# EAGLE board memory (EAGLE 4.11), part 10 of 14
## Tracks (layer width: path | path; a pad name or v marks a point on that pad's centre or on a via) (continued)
N$73  (via drill 0.61) (continued)
  Route2 0.254: v290.19,44.45 288.29,46.36 281.31,46.36 281.31,50.16 F18.F2 | v359.41,6.98 362.58,10.16 387.35,10.16 388.62,8.89 388.62,8.25 v387.99,7.62
  Route3 0.254: v324.49,4.44 328.3,4.44 330.83,1.9 359.41,1.9 v359.41,6.98
  Bottom 0.254: v392.43,12.06 393.06,11.43 398.14,11.43 404.5,17.78 410.85,17.78 417.83,24.77 420.37,24.77 F07.R2
N$74  (via drill 0.61)
  Top 0.254: C07.N2 420.37,237.49 420.37,232.41 C07.R2 | v404.5,77.47 406.4,75.56 406.4,52.7 v403.23,49.53
  Route2 0.254: v347.98,56.52 348.62,55.88 349.88,55.88 350.52,55.25 353.06,55.25 353.69,55.88 354.96,55.88 360.05,50.8 360.05,48.9 358.77,48.9 v357.5,47.62 | v373.38,38.73 381,46.36 381,48.9 v388.62,48.9 | v433.07,103.5 407.04,77.47 v404.5,77.47
  Route3 0.254: v357.5,47.62 359.41,45.72 361.95,45.72 361.95,40.01 360.68,38.73 366.39,33.02 367.67,33.02 v373.38,38.73 | F08.U2 410.85,16.51 409.57,17.78 409.57,34.29 398.78,45.09 398.78,46.99 F09.H2 | v426.72,212.72 426.72,217.17 425.45,218.44 425.45,229.23 424.18,230.5 424.18,234.31 C07.P2 | v430.53,212.72 430.53,208.28 434.98,203.84 434.98,173.99 433.7,172.72 433.7,170.18 434.98,168.91 434.98,145.41 438.15,142.24 438.15,108.58 v433.07,103.5
  Bottom 0.254: C07.R2 421,232.41 422.91,234.31 423.55,234.31 C07.P2 | v347.98,56.52 347.35,55.88 343.54,55.88 342.9,56.52 339.73,56.52 338.45,55.25 334.01,55.25 330.83,52.07 328.3,52.07 327.66,52.7 325.12,52.7 324.49,52.07 315.6,52.07 314.96,52.7 306.07,52.7 304.8,51.44 303.53,51.44 300.99,48.9 299.72,48.9 299.08,49.53 290.19,49.53 288.93,48.26 284.48,48.26 F18.H2 | v388.62,48.9 391.16,48.9 391.8,49.53 396.88,49.53 398.14,48.26 F09.H2 398.78,48.26 401.95,48.26 v403.23,49.53 | v430.53,212.72 v426.72,212.72
N$75  (via drill 0.61)
  Top 0.254: v243.21,344.17 243.21,354.97 A21.V2
  Route3 0.254: v133.35,345.44 133.35,343.54 130.18,340.36 130.18,313.06 128.91,311.79 B30.L2
  Bottom 0.254: v133.35,345.44 168.28,345.44 169.54,344.17 217.17,344.17 218.44,345.44 221.62,345.44 222.88,344.17 v243.21,344.17 | A21.U2 245.75,358.14 243.84,356.24 243.21,356.24 A21.V2
N$76  (via drill 0.61)
  Route3 0.254: v231.78,365.12 231.78,369.57 233.04,370.84 A22.P2
  Bottom 0.254: v231.78,365.12 231.78,363.86 238.76,363.86 240.03,362.59 242.57,362.59 A21.T2
N$77  (via drill 0.61)
  Top 0.254: v167.64,389.89 167.64,392.43 167,393.06 A27.F2
  Bottom 0.254: v167.64,389.89 168.28,389.25 173.35,389.25 175.9,386.72 177.8,386.72 179.07,385.45 187.96,385.45 188.59,386.08 197.49,386.08 198.12,385.45 200.66,385.45 201.29,386.08 206.38,386.08 207.65,384.81 A24.K2
N$78  (via drill 0.61)
  Top 0.254: v400.05,215.26 400.05,229.87 398.78,231.14 398.78,234.31 C09.P2
  Bottom 0.254: v400.05,215.26 379.1,215.26 378.46,214.63 350.52,214.63 349.25,215.9 332.74,215.9 332.11,216.53 332.11,218.44 C14.V2
N$79  (via drill 0.61)
  Top 0.254: v238.76,374.02 234.95,370.21 234.95,360.68 233.68,359.41 A22.U2
  Bottom 0.254: v238.76,374.02 241.94,377.19 245.75,377.19 A21.M2
N$80  (via drill 0.61)
  Top 0.254: D30.D2 128.91,194.31 130.18,195.58 130.18,219.71 131.44,220.98 131.44,221.61 C30.U2 | C32.D2 103.5,262.89 104.78,261.62 104.78,250.19 106.05,248.92 106.05,248.28 C32.K2 | C29.D2 141.6,262.89 142.88,261.62 142.88,249.56 144.15,248.28 C29.K2 | C30.N2 128.27,238.76 128.27,242.57 127,243.84 127,251.46 127.64,252.09 131.44,252.09 131.44,248.28 C30.K2 | v120.65,238.76 120.65,224.16 119.38,222.88 C31.U2
  Bottom 0.254: C32.U2 106.68,221.61 107.31,220.98 111.76,220.98 112.39,220.34 117.47,220.34 118.75,221.61 C31.U2 119.38,221.61 120.02,220.98 124.46,220.98 125.09,220.34 130.18,220.34 131.44,221.61 C30.U2 132.08,222.88 134.62,222.88 135.89,224.16 142.88,224.16 144.15,222.88 C29.U2 | C32.N2 103.5,238.76 104.78,240.03 109.86,240.03 111.12,238.76 115.57,238.76 C31.N2 116.2,238.76 116.84,239.39 120.65,239.39 | C29.N2 140.97,238.76 137.16,238.76 135.89,240.03 134.62,240.03 133.35,238.76 128.91,238.76 C30.N2 128.27,238.76 124.46,238.76 123.19,240.03 121.92,240.03 121.28,239.39 120.65,239.39 | C30.D2 128.91,264.16 130.18,265.43 135.89,265.43 137.79,263.53 140.97,263.53 C29.D2 | C32.D2 103.5,264.16 104.78,265.43 110.49,265.43 112.39,263.53 115.57,263.53 C31.D2 | C32.K2 106.68,248.28 107.31,248.92 111.76,248.92 112.39,249.56 117.47,249.56 118.75,248.28 C31.K2 119.38,248.28 121.92,248.28 123.19,249.56 130.18,249.56 131.44,248.28 C30.K2 132.08,248.28 134.62,248.28 135.89,249.56 142.88,249.56 144.15,248.28 C29.K2 | v120.65,238.76 120.65,239.39
N$81  (via drill 0.61)
  Top 0.254: v327.66,31.75 327.02,32.38 327.02,53.34 v325.12,55.25 | v392.43,231.78 391.16,230.5 391.16,229.87 390.52,229.23 390.52,224.79 v389.25,223.52 | v387.35,219.07 386.71,218.44 386.71,205.74 388.62,203.84 v388.62,201.93 | v354.33,150.5 353.69,149.86 353.69,141.6 v350.52,138.43 | v325.75,139.06 327.02,137.79 v327.02,118.74
  Route2 0.254: v369.57,153.67 368.94,154.31 364.49,154.31 360.68,150.5 v354.33,150.5 | v350.52,138.43 348.62,140.34 327.02,140.34 v325.75,139.06
  Route3 0.254: E15.H2 322.58,116.84 323.85,115.57 v323.85,82.55 323.85,56.52 v325.12,55.25 | v436.25,231.78 436.25,234.31 C06.P2 | v389.25,223.52 387.99,222.25 387.99,220.34 387.35,219.71 v387.35,219.07 | v388.62,201.93 387.35,200.66 387.35,186.06 390.52,182.88 v390.52,161.29
  Bottom 0.254: v323.85,82.55 319.4,82.55 E15.V2 | v327.66,31.75 329.56,29.84 338.45,29.84 339.09,30.48 341.63,30.48 342.26,29.84 351.15,29.84 351.79,30.48 354.33,30.48 354.96,29.84 363.86,29.84 364.49,30.48 367.03,30.48 367.67,29.84 376.56,29.84 377.19,30.48 379.73,30.48 380.37,29.84 384.81,29.84 385.44,29.21 F10.P2 | v436.25,231.78 434.98,230.5 427.99,230.5 427.36,229.87 418.46,229.87 414.65,233.68 408.94,233.68 408.31,233.04 402.59,233.04 401.95,233.68 394.33,233.68 v392.43,231.78 | v390.52,161.29 383.54,154.31 377.19,154.31 376.56,153.67 v369.57,153.67 | v327.02,118.74 325.75,117.47 322.58,117.47 E15.H2
N$82  (via drill 0.61)
  Route3 0.254: v344.81,104.14 344.81,102.23 E13.N2
  Bottom 0.254: v344.81,104.14 346.71,106.04 353.06,106.04 354.33,107.31 356.87,107.31 E12.L2
N$83  (via drill 0.61)
  Top 0.254: v308.61,93.34 307.98,93.98 307.98,102.87 306.7,104.14 306.7,107.31 E16.L2 | v384.18,71.75 384.18,43.18 385.44,41.91 F10.K2 | v367.03,71.75 366.39,72.39 v366.39,81.91 | v322.58,87.63 322.58,91.44 E15.S2
  Route3 0.254: v422.91,243.84 421.64,242.57 421.64,239.39 422.27,238.76 422.27,184.78 419.1,181.61 419.1,166.37 422.27,163.19 422.27,124.46 v419.1,121.28 | v394.97,117.47 393.7,116.2 393.7,109.85 391.16,107.31 391.16,106.04 390.52,105.41 390.52,96.52 391.8,95.25 391.8,93.98 390.52,92.71 390.52,78.1 v384.18,71.75
  Bottom 0.254: v308.61,93.34 313.06,93.34 313.69,93.98 320.68,93.98 321.94,92.71 E15.S2 | v384.18,71.75 v367.03,71.75 | v366.39,81.91 363.86,84.45 354.96,84.45 354.33,83.82 351.79,83.82 351.15,84.45 342.26,84.45 341.63,83.82 339.09,83.82 338.45,84.45 329.56,84.45 328.93,83.82 326.39,83.82 325.75,84.45 325.12,84.45 323.85,85.72 323.85,87.63 v322.58,87.63 | v422.91,243.84 425.45,246.38 427.36,246.38 427.99,245.75 434.98,245.75 436.25,247.01 C06.K2 | v419.1,121.28 413.38,115.57 402.59,115.57 399.42,118.74 396.88,118.74 395.61,117.47 v394.97,117.47
N$84  (via drill 0.61)
  Top 0.254: v306.07,97.16 306.07,99.69 304.8,100.96 v304.8,116.84 | v384.18,8.25 384.18,16.51 384.81,17.14 384.81,20.95 385.44,21.59 F10.S2 | v304.8,6.35 304.8,50.16 301.62,53.34 301.62,69.85 304.17,72.39 304.17,80.01 306.07,81.91 E16.V2
  Route2 0.254: v417.83,245.75 415.29,245.75 408.94,252.09 402.59,252.09 401.95,252.73 393.06,252.73 389.25,248.92 382.9,248.92 v379.73,245.75 | v369.57,195.58 362.58,188.59 356.24,188.59 349.88,182.25 339.09,182.25 338.45,182.88 337.82,182.88 v335.28,180.34
  Route3 0.254: v306.07,97.16 304.8,95.88 304.8,84.45 306.07,83.18 E16.V2 | v379.73,245.75 374.65,240.66 374.65,220.98 371.48,217.81 371.48,197.48 v369.57,195.58 | v335.28,180.34 336.55,179.07 336.55,151.76 v334.64,149.86 | v329.56,147.95 329.56,139.7 327.02,137.16 327.02,120.02 v325.75,118.74
  Bottom 0.254: v304.8,116.84 305.44,117.47 309.25,117.47 E16.H2 309.88,118.11 312.42,118.11 313.69,119.38 316.23,119.38 316.87,118.74 v325.75,118.74 | v384.18,8.25 383.54,7.62 361.31,7.62 360.68,8.25 350.52,8.25 348.62,6.35 346.71,6.35 345.44,7.62 334.01,7.62 333.38,6.98 308.61,6.98 307.98,6.35 v304.8,6.35 | v417.83,245.75 419.1,245.75 422.27,248.92 427.36,248.92 427.99,249.56 438.15,249.56 438.15,254.63 437.51,255.27 436.88,255.27 436.88,259.72 C06.E2 | v334.64,149.86 332.74,147.95 v329.56,147.95
N$85
  Route3 0.254: D32.V2 103.5,149.86 104.78,151.13 104.78,163.19 106.05,164.47 D32.P2
  Bottom 0.254: D29.M2 144.15,170.81 142.88,169.54 138.43,169.54 135.25,166.37 126.36,166.37 125.73,167 123.19,167 122.56,166.37 113.67,166.37 113.03,167 110.49,167 109.22,165.73 106.68,165.73 D32.P2
N$86  (via drill 0.61)
  Top 0.254: v474.35,231.14 474.35,229.23 C03.S2 | 295.27,96.52 v297.18,96.52 | 295.27,96.52 295.27,102.87 294.64,103.5 294.64,106.68 294,107.31 E17.L2 | v298.45,42.55 298.45,67.94 295.91,70.48 295.91,74.93 297.81,76.83 297.81,82.55 295.27,85.09 295.27,96.52 | v417.83,71.75 412.75,66.67 412.75,34.29 v408.31,29.84 | v392.43,33.02 389.89,33.02 388.62,34.29 386.08,34.29 F10.M2
  Route2 0.254: v485.77,151.13 487.68,149.22 487.68,141.6 488.95,140.34 488.95,135.25 487.05,135.25 485.77,133.99 485.77,132.08 485.14,132.08 428.62,75.56 421.64,75.56 v417.83,71.75
  Route3 0.254: v443.23,330.2 441.32,328.3 441.32,249.56 v439.42,247.65 | v478.15,215.26 476.25,217.17 476.25,223.52 474.98,224.79 474.98,227.97 C03.S2 | v484.5,214.63 485.77,213.36 485.77,182.25 487.05,180.97 487.05,180.34 485.77,179.07 v485.77,151.13
  Bottom 0.254: v443.23,330.2 445.77,330.2 B05.D2 | v439.42,247.65 447.04,240.03 453.39,240.03 456.56,236.85 464.19,236.85 468,233.04 472.44,233.04 v474.35,231.14 | v297.18,96.52 297.81,97.16 300.36,97.16 305.44,92.07 309.25,92.07 E16.S2 | v298.45,42.55 300.36,42.55 300.99,43.18 303.53,43.18 304.17,42.55 313.06,42.55 313.69,43.18 316.23,43.18 316.87,42.55 325.75,42.55 326.39,43.18 328.93,43.18 329.56,42.55 338.45,42.55 339.09,43.18 341.63,43.18 344.81,40.01 348.62,40.01 349.25,40.64 351.79,40.64 353.06,39.37 354.33,39.37 354.96,40.01 363.86,40.01 364.49,39.37 367.03,39.37 367.67,40.01 376.56,40.01 377.19,39.37 385.44,39.37 385.44,35.56 F10.M2 | v478.15,215.26 478.79,214.63 v484.5,214.63 | v408.31,29.84 407.67,30.48 402.59,30.48 401.95,29.84 399.42,29.84 396.24,33.02 v392.43,33.02
N$87  (via drill 0.61)
  Top 0.254: v292.1,100.96 v292.1,117.47 v292.1,123.82 | v392.43,219.07 391.8,218.44 391.8,210.82 v389.25,208.28
  Route2 0.254: v433.07,241.3 427.99,236.22 421,236.22 408.94,224.16 402.59,224.16 401.95,223.52 396.88,223.52 v392.43,219.07 | v389.25,208.28 386.71,205.74 381.63,205.74 381,205.1 352.43,205.1 332.74,185.42 332.74,182.25 330.83,182.25 v316.23,167.64
  Route3 0.254: v292.1,100.96 293.37,99.69 293.37,98.42 292.1,97.16 292.1,84.45 293.37,83.18 E17.V2 | v455.93,238.76 455.3,238.12 v455.3,236.85 | v294,164.47 288.93,159.38 288.93,153.67 287.65,152.4 287.65,151.13 290.83,147.95 290.83,138.43 292.1,137.16 v292.1,123.82
  Bottom 0.254: v292.1,117.47 296.55,117.47 E17.H2 | v455.93,238.76 457.2,240.03 465.45,240.03 466.09,239.39 473.07,239.39 474.35,240.66 C03.M2 | v455.3,236.85 454.66,236.22 444.5,236.22 438.15,242.57 434.34,242.57 v433.07,241.3 | v316.23,167.64 314.96,166.37 304.17,166.37 303.53,167 300.99,167 300.36,166.37 295.91,166.37 v294,164.47
N$88
  Top 0.254: B32.U2 106.05,289.56 104.78,290.83 104.78,296.55 103.5,297.81 B32.R2
N$89  (via drill 0.61)
  Top 0.254: v283.21,93.34 282.57,93.98 282.57,102.87 281.31,104.14 281.31,107.31 E18.L2 280.67,108.58 280.67,112.39 279.4,113.66 279.4,114.93 280.04,115.57 280.04,116.84 v279.4,117.47 | v304.17,149.22 304.17,142.88 306.07,140.97 v306.07,135.25
  Route2 0.254: v477.52,206.38 475.62,208.28 452.75,208.28 449.58,211.45 416.56,211.45 415.93,210.82 383.54,210.82 381.63,212.72 348.62,212.72 347.98,212.09 346.07,212.09 v344.81,213.36 | v341,175.26 339.73,176.53 335.92,176.53 332.74,173.35 328.3,173.35 323.85,168.91 323.85,151.13 316.87,151.13 316.23,150.5 313.69,150.5 313.06,151.13 308.61,151.13 307.98,150.5 305.44,150.5 v304.17,149.22 | v302.89,119.38 302.26,118.74 299.08,118.74 297.18,120.65 295.91,120.65 294.64,119.38 288.29,119.38 287.65,118.74 280.67,118.74 v279.4,117.47
  Route3 0.254: v477.52,206.38 480.69,209.55 480.69,214 482.6,215.9 482.6,222.88 481.96,223.52 481.96,224.79 479.43,227.33 479.43,245.11 476.25,248.28 476.25,252.09 474.98,253.36 C03.H2 | v344.81,213.36 342.9,211.45 342.9,177.16 v341,175.26 | v306.07,135.25 304.8,133.99 304.8,125.09 306.07,123.82 306.07,122.55 v302.89,119.38
  Bottom 0.254: v283.21,93.34 287.65,93.34 288.29,93.98 295.27,93.98 296.55,92.71 E17.S2
N$90  (via drill 0.61)
  Top 0.254: v278.76,115.57 278.76,113.03 279.4,112.39 279.4,84.45 280.67,83.18 E18.V2 | v405.13,287.02 405.76,286.39 405.76,278.13 401.32,273.69 v401.32,271.78 | v395.61,267.97 396.88,266.7 396.88,254.63 393.7,251.46 393.7,249.56 v394.97,248.28 | v284.48,120.02 284.48,118.11 E18.H2
  Route2 0.254: v401.32,271.78 397.51,267.97 v395.61,267.97 | v394.97,248.28 386.08,239.39 v386.08,238.12 | v385.44,198.75 381.63,194.94 379.73,194.94 376.56,191.77 370.2,191.77 358.14,179.7 353.69,179.7 321.31,147.32 306.07,147.32 v305.44,147.95
  Route3 0.254: v386.08,238.12 387.35,236.85 387.35,234.31 386.08,233.04 386.08,230.5 387.35,229.23 387.35,220.98 386.08,219.71 386.08,205.1 387.35,203.84 387.35,201.93 385.44,200.03 v385.44,198.75 | v305.44,147.95 301.62,144.14 301.62,121.92 v302.89,120.65
  Bottom 0.254: v278.76,115.57 280.67,117.47 283.85,117.47 E18.H2 | v405.13,287.02 411.48,287.02 417.83,293.37 422.27,293.37 423.55,294.64 B07.S2 | v302.89,120.65 300.99,118.74 299.08,118.74 297.18,120.65 295.91,120.65 294.64,119.38 288.29,119.38 287.65,118.74 286.38,118.74 285.12,120.02 v284.48,120.02
N$91
  Bottom 0.254: D32.T2 103.5,156.21 105.41,158.11 106.05,158.11 D32.S2
N$92
  Top 0.254: B13.T2 344.81,292.74 346.07,294 346.07,340.36 345.44,341 345.44,354.33 346.07,354.97 346.07,387.99 344.81,389.25 344.81,393.06 A13.F2
N$93  (via drill 0.61)
  Route2 0.254: v103.5,190.5 103.5,187.96 D32.F2
  Bottom 0.254: v103.5,190.5 104.78,191.77 111.76,191.77 112.39,192.41 121.28,192.41 121.92,191.77 124.46,191.77 125.09,192.41 133.99,192.41 134.62,191.77 137.16,191.77 137.79,192.41 142.88,192.41 144.15,191.13 D29.E2
N$94  (via drill 0.61)
  Top 0.254: v130.81,362.59 128.91,364.49 128.91,367.67 A30.R2 128.27,368.94 128.27,371.48 127,372.75 127,391.8 128.27,393.06 A30.F2
  Bottom 0.254: A32.F2 103.5,394.34 104.14,394.97 108.58,394.97 109.22,395.61 109.86,395.61 111.12,394.34 115.57,394.34 A31.F2 116.2,394.34 120.65,394.34 121.92,395.61 123.19,395.61 124.46,394.34 128.27,394.34 A30.F2 128.91,394.34 130.18,395.61 137.16,395.61 138.43,394.34 140.97,394.34 A29.F2 | A32.R2 103.5,368.94 107.95,368.94 109.22,370.21 109.86,370.21 111.12,368.94 115.57,368.94 A31.R2 116.2,368.94 120.02,368.94 121.28,370.21 122.56,370.21 123.83,368.94 128.27,368.94 A30.R2 | v130.81,362.59 133.35,360.05 135.25,360.05 135.89,360.68 144.78,360.68 148.59,356.87 155.57,356.87 156.84,358.14 A28.U2
N$95  (via drill 0.61)
  Top 0.254: v443.23,206.38 443.87,207.01 443.87,219.07 v442.6,220.34 | v433.7,227.33 433.7,231.14 C06.R2
  Route3 0.254: v488.95,205.74 488.95,151.76 485.77,148.59 485.77,97.16 484.5,95.88 E02.R2
  Bottom 0.254: v488.95,205.74 488.31,205.1 454.66,205.1 453.39,206.38 v443.23,206.38 | v442.6,220.34 435.61,227.33 v433.7,227.33
N$96  (via drill 0.61)
  Top 0.254: v144.15,179.7 144.15,183.51 D29.H2
  Bottom 0.254: v144.15,179.7 137.79,179.7 137.16,179.07 128.27,179.07 124.46,182.88 115.57,182.88 111.76,179.07 107.31,179.07 106.68,178.44 D32.K2
N$97  (via drill 0.61)
  Top 0.254: v503.56,170.18 504.82,168.91 504.82,140.34 501.65,137.16 v501.65,130.18
  Route2 0.254: v440.06,195.58 440.69,194.94 450.21,194.94 454.02,198.75 464.19,198.75 471.17,191.77 477.52,191.77 480.69,188.59 v480.69,187.32
  Route3 0.254: v440.06,195.58 438.15,197.48 438.15,200.66 439.42,201.93 439.42,212.72 438.15,214 438.15,222.88 434.98,226.06 434.98,242.57 433.7,243.84 C06.L2
  Bottom 0.254: v480.69,187.32 485.14,182.88 486.41,182.88 499.11,170.18 v503.56,170.18 | v501.65,130.18 501.65,113.03 493.39,113.03 488.95,108.58 484.5,108.58 E02.L2
N$98
  Bottom 0.254: D32.N2 103.5,168.91 104.78,170.18 111.76,170.18 112.39,169.54 114.94,169.54 118.11,172.72 124.46,172.72 125.09,173.35 132.72,173.35 133.35,172.72 135.89,172.72 140.34,177.16 144.15,177.16 D29.K2
N$100  (via drill 0.61)
  Route3 0.254: v480.69,142.88 482.6,140.97 482.6,122.55 483.87,121.28 E02.F2 | v440.06,144.14 438.79,145.41 v438.79,147.95 | v429.89,154.94 425.45,159.38 425.45,210.19 431.8,216.53 431.8,255.27 433.07,256.54 C06.F2
  Bottom 0.254: v480.69,142.88 480.06,143.51 459.11,143.51 458.47,144.14 v440.06,144.14 | v438.79,147.95 431.8,154.94 v429.89,154.94
N$102  (via drill 0.61)
  Top 0.254: v270.51,93.34 269.88,93.98 269.88,102.87 268.61,104.14 268.61,107.31 E19.L2
  Route2 0.254: v354.33,311.15 355.6,312.42 359.41,312.42 365.76,306.07 373.38,306.07 377.19,309.88 387.35,309.88 394.33,302.9 401.95,302.9 405.76,306.71 416.56,306.71 419.74,303.53 423.55,303.53 423.55,307.34 B07.M2 | v344.17,240.66 336.55,233.04 326.39,233.04 325.75,233.68 323.85,233.68 321.94,231.78 321.31,231.78 320.04,233.04 313.69,233.04 313.06,233.68 307.98,233.68 303.53,238.12 302.26,238.12 300.36,236.22 294,236.22 281.94,224.16 277.5,224.16 v271.78,218.44 | v266.7,177.8 266.7,175.89 262.89,175.89 262.25,176.53 260.99,176.53 254,169.54 254,152.4 v255.27,152.4 | v255.91,116.2 262.89,109.22 267.33,109.22 267.97,108.58 E19.L2
  Route3 0.254: v354.33,311.15 352.43,309.25 352.43,302.9 351.15,301.62 351.15,300.36 352.43,299.09 352.43,279.4 350.52,277.5 v350.52,271.78 | v344.17,271.78 342.9,270.51 342.9,267.97 344.17,266.7 344.17,265.43 342.9,264.16 342.9,261.62 346.07,258.44 346.07,242.57 v344.17,240.66 | v271.78,218.44 267.97,214.63 267.97,205.1 266.7,203.84 266.7,187.96 263.52,184.78 263.52,181.61 266.7,178.44 v266.7,177.8 | v255.27,152.4 257.18,150.5 257.18,117.47 v255.91,116.2
  Bottom 0.254: v270.51,93.34 274.95,93.34 275.59,93.98 278.13,93.98 280.04,92.07 283.85,92.07 E18.S2 | v344.17,271.78 v350.52,271.78
N$104  (via drill 0.61)
  Top 0.254: v485.77,180.97 485.77,154.31 487.05,153.03 D02.U2 | v476.88,184.15 476.25,184.78 v476.25,224.79
  Bottom 0.254: v485.77,180.97 485.77,182.25 478.79,182.25 v476.88,184.15 | v476.25,224.79 475.62,225.42 471.81,225.42 C03.T2
N$106  (via drill 0.61)
  Top 0.254: v266.06,88.9 266.7,89.53 266.7,105.41 263.52,108.58 v263.52,114.3 | v288.29,307.34 288.93,306.71 288.93,290.83 v287.02,288.93
  Route2 0.254: v266.06,88.9 267.33,87.63 267.97,87.63 267.97,83.18 E19.V2 | v393.06,319.41 392.43,318.77 389.89,318.77 386.08,322.58 377.19,322.58 376.56,321.95 367.67,321.95 367.03,322.58 364.49,322.58 363.86,321.95 354.96,321.95 354.33,322.58 351.79,322.58 351.15,321.95 342.26,321.95 341.63,322.58 340.36,322.58 336.55,318.77 326.39,318.77 325.75,319.41 316.87,319.41 316.23,318.77 313.69,318.77 313.06,319.41 304.17,319.41 303.53,318.77 300.99,318.77 300.36,319.41 298.45,319.41 287.65,308.61 287.65,307.34 v288.29,307.34 | v287.02,288.93 285.12,290.83 275.59,290.83 271.78,287.02 v265.43,287.02 | v220.98,133.99 226.69,128.27 233.04,128.27 239.4,121.92 248.28,121.92 248.92,122.55 251.46,122.55 252.09,121.92 257.18,121.92 263.52,115.57 v263.52,114.3
  Route3 0.254: v265.43,287.02 264.16,285.75 264.16,276.23 266.7,273.69 266.7,252.73 v264.8,250.82 | v236.22,247.65 222.25,233.68 222.25,218.44 217.17,213.36 217.17,201.93 215.9,200.66 215.9,165.73 217.17,164.47 217.17,163.83 215.9,162.56 215.9,148.59 219.07,145.41 219.07,135.89 v220.98,133.99
  Bottom 0.254: v263.52,114.3 264.8,115.57 269.88,115.57 271.14,116.84 E19.H2 | v393.06,319.41 401.95,319.41 402.59,318.77 411.48,318.77 415.29,322.58 422.27,322.58 423.55,321.31 B07.H2 | v264.8,250.82 262.89,248.92 253.37,248.92 252.73,249.56 250.19,249.56 249.56,248.92 240.66,248.92 240.03,249.56 238.76,249.56 236.85,247.65 v236.22,247.65
N$107  (via drill 0.61)
  Top 0.254: v398.78,220.34 397.51,219.07 397.51,217.81 398.14,217.17 398.14,205.1 396.24,203.2 396.24,201.29 396.88,200.66 396.88,197.48 v394.97,195.58 | v328.3,147.95 330.2,146.05 330.2,114.93 327.02,111.76 327.02,106.68 v325.12,104.77
  Route2 0.254: E20.L2 255.91,107.31 255.91,102.87 258.44,102.87 266.7,94.61 266.7,92.07 271.14,92.07 E19.S2 | v439.42,234.95 437.51,233.04 427.99,233.04 427.36,233.68 419.74,233.68 408.94,222.88 407.67,222.88 405.13,220.34 402.59,220.34 401.95,220.98 399.42,220.98 v398.78,220.34 | v394.97,195.58 391.16,191.77 383.54,191.77 v373.38,181.61 | v353.69,163.19 353.06,163.83 344.17,163.83 v328.3,147.95 | v325.12,104.77 323.85,106.04 320.68,106.04 314.32,99.69 304.17,99.69 297.18,106.68 288.29,106.68 287.65,106.04 278.76,106.04 274.95,109.85 273.05,109.85 v271.78,108.58
  Route3 0.254: v439.42,234.95 441.32,236.85 441.32,240.03 438.15,243.2 438.15,248.28 434.98,251.46 434.98,273.69 435.61,274.32 435.61,287.66 436.25,288.29 B06.U2 | v373.38,181.61 374.01,180.97 374.01,179.07 374.65,178.44 374.65,172.09 v375.92,170.81
  Bottom 0.254: v375.92,170.81 372.11,167 364.49,167 360.68,163.19 v353.69,163.19 | v271.78,108.58 269.88,106.68 262.89,106.68 262.25,106.04 257.18,106.04 255.91,107.31 E20.L2
N$109  (via drill 0.61)
  Top 0.254: v474.98,168.91 473.07,170.81 473.07,236.22 471.81,237.49 C03.N2
  Bottom 0.254: v474.98,168.91 477.52,166.37 478.15,166.37 478.79,167 485.77,167 487.05,165.73 D02.P2
N$110  (via drill 0.61)
  Top 0.254: v414.65,338.46 414.02,339.09 v414.02,346.71 | v276.23,316.87 v276.23,330.2 | v263.52,227.97 v263.52,197.48
  Route2 0.254: v414.65,338.46 415.93,338.46 415.93,325.75 427.36,314.33 427.99,314.33 435.61,306.71 436.25,306.71 436.25,302.26 B06.P2 | v414.02,346.71 413.38,346.08 406.4,346.08 404.5,347.98 377.82,347.98 374.65,351.16 352.43,351.16 349.88,353.7 329.56,353.7 320.04,363.22 313.69,363.22 313.06,363.86 308.61,363.86 307.98,363.22 301.62,363.22 v299.72,365.12 | v271.14,297.81 270.51,297.18 264.8,297.18 259.08,291.47 v257.81,291.47 | v263.52,197.48 231.78,165.73 231.78,143.51 234.95,143.51 237.49,140.97 240.03,140.97 v243.21,137.79
  Route3 0.254: v250.82,114.3 250.82,110.49 254,107.31 254,84.45 255.27,83.18 E20.V2 | v299.72,365.12 291.46,373.38 288.29,373.38 276.23,361.31 v276.23,330.2 | v276.23,316.87 276.23,304.17 271.14,299.09 v271.14,297.81 | v257.81,291.47 257.18,290.83 257.18,274.32 250.82,267.97 250.82,240.03 253.37,237.49 253.37,236.85 255.27,234.95 255.27,233.68 254,232.41 254,231.14 v255.91,229.23 | v243.21,137.79 244.47,136.53 244.47,121.92 v245.75,120.65
  Bottom 0.254: 251.46,114.93 252.09,115.57 254,115.57 255.91,117.47 258.44,117.47 E20.H2 | 251.46,114.93 v250.82,114.3 | v255.91,229.23 256.54,229.87 260.35,229.87 262.25,227.97 v263.52,227.97 | v245.75,120.65 251.46,114.93
N$112  (via drill 0.61)
  Top 0.254: v482.6,177.8 482.6,229.87 v480.69,231.78 | v474.98,237.49 473.07,239.39 473.07,245.75 471.81,247.01 471.81,250.19 C03.J2
  Route2 0.254: v480.69,231.78 v474.98,237.49
  Bottom 0.254: v482.6,177.8 487.05,177.8 D02.K2
N$113  (via drill 0.61)
  Top 0.254: v427.36,281.31 425.45,283.21 425.45,287.02 426.72,288.29 v426.72,290.2
  Route3 0.254: v484.5,278.77 488.95,274.32 488.95,256.54 490.22,255.27 488.95,254 488.95,224.16 487.68,222.88 C02.U2
  Bottom 0.254: v484.5,278.77 481.96,281.31 v427.36,281.31 | v426.72,290.2 425.45,291.47 421,291.47 B07.T2
N$114  (via drill 0.61)
  Top 0.254: v419.74,297.18 419.1,297.81 419.1,299.09 420.37,300.36 420.37,304.17 B07.N2
  Bottom 0.254: v419.74,297.18 424.18,297.18 427.99,293.37 431.17,293.37 431.17,292.1 422.27,283.21 419.74,283.21 419.74,280.04 424.18,275.59 432.44,275.59 433.7,276.86 446.4,276.86 447.68,275.59 480.69,275.59 487.05,269.24 488.95,269.24 488.95,256.54 493.39,252.09 498.48,252.09 498.48,247.01 499.11,246.38 501.01,246.38 501.01,245.11 492.12,236.22 488.31,236.22 487.68,235.59 C02.P2
N$115  (via drill 0.61)
  Route3 0.254: v433.07,273.05 434.98,274.96 v434.98,311.79
  Bottom 0.254: v433.07,273.05 434.34,274.32 437.51,274.32 438.15,273.69 439.42,273.69 441.96,276.23 445.77,276.23 447.04,274.96 474.98,274.96 485.14,264.8 485.77,264.8 485.77,256.54 485.14,255.91 482.6,255.91 482.6,249.56 484.5,247.65 487.05,247.65 C02.K2 | v434.98,311.79 434.34,312.42 427.99,312.42 423.55,316.87 421,316.87 B07.J2
N$116  (via drill 0.61)
  Top 0.254: v483.87,281.94 485.77,280.04 485.77,262.25 487.05,260.99 C02.E2
  Bottom 0.254: v483.87,281.94 433.07,281.94 433.07,285.12 B06.V2
N$117  (via drill 0.61)
  Route3 0.254: v483.87,288.93 483.87,291.47 B02.T2
  Bottom 0.254: v483.87,288.93 478.79,283.85 445.77,283.85 433.7,295.91 433.7,297.81 B06.R2
N$118
  Bottom 0.254: B02.N2 483.87,304.8 480.06,304.8 475.62,309.25 469.26,309.25 468.63,309.88 466.09,309.88 465.45,309.25 456.56,309.25 455.93,309.88 453.39,309.88 452.75,309.25 443.87,309.25 443.23,309.88 440.69,309.88 440.06,309.25 434.98,309.25 433.7,310.52 B06.L2
N$119  (via drill 0.61)
  Top 0.254: v53.98,73.02 53.98,52.7 52.7,51.44 F36.F2
  Route2 0.254: v135.25,228.6 165.74,259.08 175.26,259.08 175.9,258.44 184.78,258.44 188.59,262.25 197.49,262.25 198.12,261.62 200.66,261.62 204.47,265.43 213.36,265.43 214,264.8 222.88,264.8 223.52,265.43 226.06,265.43 229.24,262.25 231.78,262.25 234.95,265.43 238.76,265.43 239.4,264.8 247.65,264.8 257.81,274.96 265.43,274.96 272.42,267.97 276.86,267.97 v277.5,268.61
  Route3 0.254: v93.34,75.56 95.25,77.47 95.25,151.76 98.42,154.94 98.42,193.04 107.95,202.56 107.95,220.98 v110.49,223.52 | v277.5,268.61 282.57,273.69 282.57,313.69 271.78,324.49 271.78,326.39 B19.E2
  Bottom 0.254: v53.98,73.02 53.98,76.83 85.72,76.83 87,75.56 v93.34,75.56 | v110.49,223.52 111.12,224.16 121.28,224.16 121.92,223.52 123.19,223.52 127,227.33 133.99,227.33 v135.25,228.6
N$120  (via drill 0.61)
  Top 0.254: v365.76,236.22 361.95,236.22 v361.95,256.54
  Bottom 0.254: v365.76,236.22 366.39,236.85 367.03,236.85 367.67,236.22 372.11,236.22 372.75,235.59 C11.P2 | v361.95,256.54 357.5,256.54 C12.F2
N$121  (via drill 0.61)
  Top 0.254: v349.25,374.65 349.25,382.27 347.98,383.54 A13.K2 347.35,384.81 347.35,387.99 346.07,389.25 346.07,394.97 v341,394.97
  Route2 0.254: v349.25,374.65 344.81,374.65 A13.N2
  Bottom 0.254: v341,394.97 340.36,395.61 333.38,395.61 332.11,394.34 A14.F2
N$122
  Bottom 0.254: A15.H2 321.94,391.16 320.04,393.06 319.4,393.06 A15.F2
N$125  (via drill 0.61)
  Top 0.254: v351.79,379.1 352.43,379.73 352.43,391.16 354.33,393.06 356.87,393.06 A12.F2
  Bottom 0.254: v351.79,379.1 350.52,379.1 349.88,379.73 341,379.73 340.36,379.1 335.92,379.1 335.28,378.46 A14.M2
N$126
  Top 0.254: A39.V2 14.61,356.24 15.88,357.5 15.88,363.22 17.14,364.49 A39.S2
  Bottom 0.254: A39.N2 14.61,374.02 14.61,369.57 15.24,369.57 17.14,367.67 17.14,365.76 A39.S2 17.78,364.49 18.41,363.86 22.86,363.86 24.13,362.59 26.67,362.59 A38.T2 27.3,361.31 29.84,361.31 34.29,356.87 36.83,356.87 37.47,357.5 46.35,357.5 46.99,356.87 49.53,356.87 50.16,357.5 59.05,357.5 59.69,356.87 66.67,356.87 67.94,358.14 A35.U2
N$127  (via drill 0.61)
  Top 0.254: v372.75,243.2 372.75,247.01 C11.K2
  Bottom 0.254: v372.75,243.2 366.39,243.2 365.76,242.57 361.31,242.57 360.68,241.94 C12.M2
N$128  (via drill 0.61)
  Top 0.254: v317.5,351.79 v317.5,329.56 | v279.4,354.97 v279.4,370.84
  Route3 0.254: v317.5,329.56 317.5,325.75 318.77,324.49 B15.F2
  Bottom 0.254: v317.5,351.79 316.87,352.43 297.81,352.43 296.55,353.7 280.67,353.7 v279.4,354.97 | v279.4,370.84 280.04,371.48 283.85,371.48 A18.P2
N$129  (via drill 0.61)
  Top 0.254: v396.88,280.04 400.05,276.86 400.05,255.91 398.78,254.63 C09.H2
  Route3 0.254: v371.48,280.67 360.68,291.47 360.68,294.64 B12.S2
  Bottom 0.254: v396.88,280.04 394.97,281.94 372.75,281.94 v371.48,280.67
N$130  (via drill 0.61)
  Route2 0.254: v387.35,284.48 384.81,287.02 377.19,287.02 376.56,287.66 367.67,287.66 367.03,287.02 364.49,287.02 360.05,291.47 357.5,291.47 B12.T2
  Route3 0.254: v387.35,284.48 386.08,283.21 386.08,279.4 387.35,278.13 387.35,241.94 390.52,238.76 390.52,227.97 393.7,224.79 393.7,222.88 398.14,222.88 C09.U2
N$131  (via drill 0.61)
  Top 0.254: v350.52,247.65 352.43,249.56 352.43,262.89 355.6,266.06 v355.6,280.67 | v369.57,280.67 371.48,282.58 371.48,293.37 372.75,294.64 B11.S2
  Route2 0.254: v350.52,247.65 347.98,247.65 C13.K2
  Bottom 0.254: v355.6,280.67 356.24,280.04 367.67,280.04 368.3,280.67 v369.57,280.67
N$132  (via drill 0.61)
  Top 0.254: v342.9,260.35 v342.9,266.7 | v347.35,268.61 346.71,269.24 346.71,271.78 345.44,273.05 v345.44,284.48
  Route2 0.254: v342.9,260.35 347.35,260.35 C13.E2
  Route3 0.254: v373.38,284.48 374.65,285.75 374.65,318.77 373.38,320.04 B11.H2
  Bottom 0.254: v342.9,266.7 344.81,268.61 v347.35,268.61 | v345.44,284.48 346.07,283.85 366.39,283.85 367.03,284.48 v373.38,284.48
N$133  (via drill 0.61)
  Top 0.254: v356.87,281.31 355.6,282.58 v355.6,297.18 | v369.57,313.69 369.57,316.87 B11.J2
  Route2 0.254: v347.98,278.77 347.98,281.94 356.24,281.94 v356.87,281.31
  Route3 0.254: v347.98,278.77 346.07,276.86 346.07,259.72 346.71,259.08 346.71,255.27 347.35,254.63 C13.H2 | v355.6,297.18 355.6,306.71 v356.87,307.98
  Bottom 0.254: v356.87,307.98 358.14,309.25 365.12,309.25 v369.57,313.69
N$134  (via drill 0.61)
  Route3 0.254: v351.15,234.95 352.43,236.22 352.43,248.28 351.79,248.92 351.79,249.56 352.43,250.19 352.43,262.89 353.69,264.16 353.69,264.8 352.43,266.06 352.43,276.86 354.33,278.77 354.33,287.02 355.6,288.29 355.6,293.37 v356.87,294.64 | v386.08,297.18 387.35,298.45 387.35,318.77 386.08,320.04 B10.H2
  Bottom 0.254: v351.15,234.95 347.98,234.95 C13.P2 | v356.87,294.64 358.77,296.55 365.76,296.55 366.39,297.18 375.29,297.18 375.92,296.55 378.46,296.55 379.1,297.18 v386.08,297.18
N$135  (via drill 0.61)
  Route2 0.254: v372.75,238.12 371.48,238.12 371.48,234.95 369.57,233.04 368.94,233.04 365.76,229.87 363.22,229.87 362.58,230.5 353.69,230.5 353.06,229.87 348.62,229.87 347.98,229.23 C13.S2
  Route3 0.254: v372.75,238.12 372.11,238.76 372.11,240.03 371.48,240.66 371.48,250.19 374.65,253.36 374.65,264.8 377.82,267.97 377.82,310.52 382.27,314.96 382.27,316.87 B10.J2
N$136  (via drill 0.61)
  Top 0.254: v333.38,298.45 333.38,291.47 332.74,290.83 332.74,287.02 332.11,286.39 B14.V2 | v351.15,302.9 352.43,304.17 352.43,310.52 356.87,314.96 356.87,316.87 B12.J2
  Route3 0.254: v398.14,280.04 396.88,278.77 396.88,262.25 398.14,260.99 C09.E2
  Bottom 0.254: v333.38,298.45 333.38,302.9 340.36,302.9 341,303.53 349.88,303.53 350.52,302.9 v351.15,302.9 | v398.14,280.04 395.61,282.58 368.94,282.58 367.67,283.85 367.03,283.21 342.9,283.21 342.26,283.85 333.38,283.85 332.11,285.12 B14.V2
N$137  (via drill 0.61)
  Top 0.254: v302.89,317.5 304.8,319.41 v304.8,344.81 | v337.82,342.9 341.63,342.9 v341.63,350.52 | v396.24,352.43 396.88,353.06 396.88,356.87 395.61,358.14 395.61,361.31 A09.T2 | v271.78,37.46 266.7,42.55 266.7,75.56 269.88,78.74 269.88,91.44 v267.97,93.34 | v265.43,107.95 266.7,109.22 266.7,157.48 v268.61,159.38 | v287.02,165.1 288.29,166.37 288.29,167 288.93,167.64 v288.93,183.51 | v353.69,187.32 355.6,189.23 355.6,199.39 351.15,203.84 351.15,217.17 352.43,218.44 352.43,230.5 356.87,234.95 356.87,237.49 C12.N2 | v396.88,287.66 396.88,299.72 398.14,300.99 B09.P2
  Route2 0.254: v346.07,188.59 346.71,189.23 351.79,189.23 v353.69,187.32
  Route3 0.254: v396.24,352.43 396.88,351.79 396.88,326.39 400.05,323.22 400.05,303.53 398.78,302.26 B09.P2 | v267.97,93.34 266.7,94.61 266.7,105.41 265.43,106.68 v265.43,107.95 | v379.73,284.48 379.1,283.85 v379.1,280.04 | v370.84,279.4 361.95,270.51 361.95,257.81 360.68,256.54 360.68,255.91 361.95,254.63 361.95,246.38 360.05,244.47 358.77,244.47 358.77,245.11 358.14,245.75 355.6,245.75 355.6,241.94 356.87,240.66 356.87,238.76 C12.N2
  Bottom 0.254: v302.89,317.5 300.99,319.41 295.91,319.41 294.64,320.68 292.1,320.68 292.1,316.87 293.37,315.6 295.91,315.6 296.55,314.96 B17.K2 | v304.8,344.81 306.7,342.9 v337.82,342.9 | v341.63,350.52 357.5,350.52 359.41,352.43 v396.24,352.43 | v271.78,37.46 274.32,40.01 274.95,40.01 275.59,39.37 280.04,39.37 280.67,38.73 F18.L2 | v268.61,159.38 269.24,160.02 275.59,160.02 279.4,163.83 285.75,163.83 v287.02,165.1 | v288.93,183.51 290.19,182.25 291.46,182.25 294.64,185.42 302.26,185.42 302.89,186.06 304.17,186.06 304.8,185.42 314.96,185.42 318.77,189.23 327.66,189.23 328.3,188.59 337.19,188.59 337.82,189.23 340.36,189.23 341,188.59 v346.07,188.59 | v396.88,287.66 396.24,287.02 389.89,287.02 389.25,287.66 386.71,287.66 383.54,284.48 v379.73,284.48 | v379.1,280.04 378.46,279.4 v370.84,279.4
N$138
  Top 0.254: B10.L2 382.9,311.79 384.18,313.06 384.18,353.7 382.9,354.97 A10.V2
N$139  (via drill 0.61)
  Top 0.254: v367.67,282.58 368.3,283.21 368.3,307.34 370.2,309.25 370.2,310.52 B11.L2 | v406.4,314.96 406.4,321.95 407.67,323.22 B08.F2
  Bottom 0.254: v367.67,282.58 342.26,282.58 341.63,283.21 332.74,283.21 332.11,283.85 295.27,283.85 294,285.12 B17.V2 | v406.4,314.96 406.4,312.42 402.59,312.42 401.95,313.06 393.06,313.06 392.43,312.42 389.89,312.42 389.25,313.06 380.37,313.06 379.73,312.42 377.19,312.42 376.56,313.06 371.48,313.06 370.2,311.79 B11.L2
N$140  (via drill 0.61)
  Top 0.254: v370.2,290.2 370.2,286.39 B11.V2 | v371.48,386.72 v371.48,320.04 | v322.58,387.35 322.58,384.81 A15.K2
  Route3 0.254: v370.2,290.2 371.48,291.47 v371.48,320.04
  Bottom 0.254: A09.F2 394.97,393.06 392.43,393.06 391.16,391.8 388.62,391.8 387.99,392.43 379.1,392.43 377.82,391.16 375.92,391.16 v371.48,386.72 370.84,386.08 366.39,386.08 365.76,385.45 363.22,385.45 362.58,386.08 353.69,386.08 353.06,385.45 342.26,385.45 338.45,389.25 337.82,389.25 337.19,388.62 328.3,388.62 327.66,389.25 324.49,389.25 v322.58,387.35
N$141  (via drill 0.61)
  Top 0.254: v321.94,299.72 321.31,299.09 321.31,296.55 320.68,295.91 320.68,294 v322.58,292.1
  Bottom 0.254: v321.94,299.72 315.6,299.72 314.96,300.36 312.42,300.36 311.79,299.72 302.89,299.72 302.26,300.36 294,300.36 294,304.17 B17.N2 | v322.58,292.1 324.49,290.2 327.66,290.2 328.3,290.83 337.19,290.83 337.82,290.2 340.36,290.2 341,290.83 347.35,290.83 347.98,290.2 348.62,290.2 352.43,286.39 356.87,286.39 B12.V2
N$142  (via drill 0.61)
  Top 0.254: v400.05,294 v400.05,324.49
  Bottom 0.254: v400.05,294 396.88,294 395.61,292.74 B09.T2 | v400.05,324.49 404.5,328.93 409.57,328.93 410.85,327.66 B08.E2
N$143  (via drill 0.61)
  Top 0.254: v347.98,213.36 347.98,221.61 C13.U2 | v412.75,212.09 412.75,226.69 411.48,227.97 C08.S2 | v402.59,277.5 400.05,280.04 400.05,289.56 398.78,290.83 398.78,294.64 B09.S2 | v350.52,358.78 352.43,356.87 352.43,342.27 v351.15,341
  Route3 0.254: v402.59,277.5 401.95,276.86 401.95,272.42 403.23,271.15 403.23,233.04 v404.5,231.78 | v388.62,339.73 387.35,338.46 387.35,321.31 396.88,311.79 396.88,297.18 398.14,295.91 B09.S2
  Bottom 0.254: v347.98,213.36 348.62,212.72 380.37,212.72 381,213.36 387.35,213.36 389.25,211.45 412.12,211.45 v412.75,212.09 | v404.5,231.78 405.76,231.78 408.31,229.23 410.85,229.23 C08.S2 | v350.52,358.78 349.25,357.5 346.07,357.5 344.81,356.24 A13.V2 | v351.15,341 351.79,341.63 361.31,341.63 361.95,341 365.76,341 366.39,341.63 372.75,341.63 373.38,341 378.46,341 379.1,341.63 386.71,341.63 v388.62,339.73
N$144  (via drill 0.61)
  Top 0.254: v395.61,246.38 393.06,248.92 393.06,252.73 393.7,253.36 393.7,273.69 388.62,278.77 v388.62,283.85 | v385.44,285.12 384.18,286.39 v384.18,307.34 | v368.94,309.25 368.3,309.88 v368.3,320.04 | v355.6,320.68 355.6,372.75 356.87,374.02 A12.N2
  Route2 0.254: v388.62,283.85 387.99,283.21 387.35,283.21 v385.44,285.12
  Route3 0.254: v395.61,246.38 396.88,245.11 396.88,230.5 398.14,229.23 C09.S2
  Bottom 0.254: v384.18,307.34 381.63,309.88 377.19,309.88 376.56,309.25 v368.94,309.25 | v368.3,320.04 368.3,322.58 365.76,322.58 364.49,321.31 360.68,321.31 B12.H2 360.05,320.68 v355.6,320.68
N$145  (via drill 0.61)
  Route2 0.254: v466.09,385.45 464.82,385.45 461.64,388.62 455.3,388.62 454.66,389.25 448.31,389.25 441.96,395.61 434.98,395.61 433.7,394.34 A06.F2
  Bottom 0.254: v466.09,385.45 466.73,386.08 476.88,386.08 484.5,378.46 487.05,378.46 A02.M2
N$146  (via drill 0.61)
  Top 0.254: v474.35,373.38 487.05,386.08 487.05,389.89 A02.H2
  Route2 0.254: v474.35,373.38 468,373.38 467.36,372.75 464.82,372.75 464.19,373.38 455.3,373.38 454.66,372.75 447.68,372.75 446.4,374.02 A05.N2
N$147  (via drill 0.61)
  Top 0.254: v453.39,390.53 447.68,384.81 447.68,382.91 446.4,381.64 A05.L2
  Bottom 0.254: v453.39,390.53 455.3,392.43 456.56,392.43 457.2,391.8 467.36,391.8 468,392.43 476.88,392.43 477.52,391.8 480.06,391.8 481.33,393.06 483.87,393.06 A02.F2
N$148  (via drill 0.61)
  Top 0.254: v353.69,297.18 355.6,299.09 355.6,309.25 356.87,310.52 B12.L2
  Bottom 0.254: v353.69,297.18 353.06,296.55 349.25,296.55 348.62,297.18 341,297.18 340.36,296.55 337.82,296.55 337.19,297.18 328.3,297.18 327.66,296.55 323.21,296.55 322.58,295.91 B15.S2
N$149  (via drill 0.61)
  Top 0.254: v480.69,355.6 482.6,357.5 482.6,379.1 483.87,380.37 A02.L2
  Bottom 0.254: v480.69,355.6 478.79,353.7 447.68,353.7 446.4,354.97 A05.V2
N$150
  Bottom 0.254: A05.R2 446.4,367.67 447.68,366.4 454.66,366.4 458.47,370.21 467.36,370.21 471.17,366.4 480.06,366.4 483.87,370.21 488.31,370.21 488.95,370.84 488.95,386.72 484.5,386.72 A02.J2
N$151  (via drill 0.61)
  Top 0.254: v447.68,352.43 447.68,360.05 446.4,361.31 A05.T2 | v483.87,352.43 485.77,354.33 485.77,382.27 487.05,383.54 A02.K2
  Bottom 0.254: v447.68,352.43 448.31,353.06 483.24,353.06 v483.87,352.43
N$152  (via drill 0.61)
  Top 0.254: v293.37,384.81 298.45,379.73 v298.45,353.7
  Route3 0.254: v332.11,358.14 332.11,356.24 A14.V2
  Bottom 0.254: v293.37,384.81 288.93,389.25 285.12,389.25 284.48,389.89 A18.H2 | v298.45,353.7 327.02,353.7 328.3,354.97 331.47,354.97 A14.V2 | v332.11,358.14 334.64,358.14 A14.U2
N$153
  Route3 0.254: B15.K2 322.58,314.96 323.85,316.23 323.85,375.92 322.58,377.19 A15.M2
N$154
  Bottom 0.254: A14.T2 332.11,362.59 333.38,363.86 340.36,363.86 341,363.22 346.07,363.22 347.35,364.49 A13.S2
N$155
  Bottom 0.254: B13.H2 347.35,320.04 347.35,317.5 346.71,316.87 346.71,315.6 353.06,315.6 353.69,316.23 362.58,316.23 363.22,315.6 364.49,315.6 365.76,316.87 368.3,316.87 369.57,315.6 377.19,315.6 378.46,316.87 381,316.87 382.27,315.6 391.16,315.6 391.8,316.23 400.69,316.23 401.32,315.6 403.86,315.6 404.5,316.23 409.57,316.23 410.85,314.96 B08.K2
N$156
  Top 0.254: B14.K2 334.64,314.96 333.38,316.23 333.38,321.95 332.11,323.22 B14.F2
  Bottom 0.254: B13.F2 344.17,324.49 339.73,324.49 338.45,325.75 337.82,325.75 336.55,324.49 332.11,324.49 B14.F2
N$157  (via drill 0.61)
  Top 0.254: v398.14,238.12 397.51,238.76 397.51,240.03 396.88,240.66 v396.88,249.56 | v408.31,254.63 408.31,256.54 C08.F2 | v333.38,247.65 333.38,289.56 334.01,290.2 334.01,294 334.64,294.64 B14.S2
  Route2 0.254: v398.14,238.12 396.88,238.12 396.88,231.14 392.43,226.69 391.8,226.69 391.16,227.33 388.62,227.33 387.35,226.06 382.9,226.06 C10.T2
  Bottom 0.254: 399.42,252.09 400.05,252.73 403.86,252.73 404.5,252.09 405.76,252.09 v408.31,254.63 | 399.42,252.09 v396.88,249.56 | v333.38,247.65 333.38,246.38 340.36,246.38 341,245.75 349.88,245.75 350.52,246.38 353.06,246.38 353.69,245.75 356.24,245.75 359.41,248.92 365.76,248.92 366.39,249.56 375.29,249.56 375.92,248.92 378.46,248.92 379.1,249.56 385.44,249.56 388.62,252.73 391.16,252.73 391.8,252.09 399.42,252.09
N$158  (via drill 0.61)
  Top 0.254: C10.V2 382.9,219.71 385.44,222.25 C10.U2 | v401.32,228.6 401.32,229.87 400.05,231.14 400.05,237.49 398.78,238.76 398.78,240.66 C09.M2
  Bottom 0.254: v401.32,228.6 396.88,224.16 391.16,224.16 389.25,222.25 386.08,222.25 C10.U2
N$159  (via drill 0.61)
  Top 0.254: v371.48,251.46 371.48,230.5 372.75,229.23 C11.S2 | v382.27,254.63 382.27,256.54 C10.F2
  Bottom 0.254: v371.48,251.46 372.75,252.73 378.46,252.73 379.1,252.09 379.73,252.09 v382.27,254.63
N$160  (via drill 0.61)
  Top 0.254: v455.93,394.34 449.58,387.99 446.4,387.99 A05.J2
  Bottom 0.254: v455.93,394.34 457.2,395.61 467.36,395.61 468,394.97 476.88,394.97 477.52,395.61 480.06,395.61 480.69,394.97 485.77,394.97 487.05,396.24 A02.E2
N$161  (via drill 0.61)
  Top 0.254: v410.85,317.5 410.85,316.87 409.57,315.6 409.57,294.64 410.21,294 410.21,290.2 410.85,289.56 B08.U2
  Route3 0.254: v410.85,317.5 406.4,321.95 406.4,343.54 396.24,353.7 387.35,353.7 387.35,363.22 386.08,364.49 A10.S2
N$162  (via drill 0.61)
  Top 0.254: v321.94,311.15 320.04,309.25 320.04,306.07 319.4,305.44 B15.N2 | v391.8,361.95 393.7,363.86 393.7,375.29 395.61,377.19 398.14,377.19 A09.M2
  Route2 0.254: v321.94,311.15 323.85,313.06 327.66,313.06 328.3,312.42 328.93,312.42 331.47,314.96 v333.38,314.96
  Route3 0.254: v333.38,314.96 333.38,323.22 342.9,332.74 342.9,337.82 345.44,340.36 345.44,354.33 346.07,354.97 346.07,359.41 v347.35,360.68
  Bottom 0.254: v347.35,360.68 353.69,367.03 362.58,367.03 363.22,366.4 365.76,366.4 366.39,367.03 375.29,367.03 379.1,363.22 387.99,363.22 388.62,363.86 389.89,363.86 v391.8,361.95
N$163
  Bottom 0.254: C11.M2 373.38,241.94 374.01,242.57 378.46,242.57 379.1,243.2 384.18,243.2 385.44,241.94 C10.M2
N$164  (via drill 0.61)
  Top 0.254: v400.05,238.76 400.05,245.75 398.78,247.01 C09.K2
  Bottom 0.254: C10.N2 382.9,237.49 383.54,237.49 385.44,235.59 C10.P2 386.08,235.59 388.62,235.59 389.89,236.85 398.14,236.85 v400.05,238.76
N$165
  Bottom 0.254: B23.F2 217.81,324.49 219.07,325.75 226.06,325.75 226.69,325.12 235.59,325.12 236.22,325.75 238.76,325.75 240.03,324.49 242.57,324.49 B21.F2
N$166  (via drill 0.61)
  Top 0.254: v417.19,304.8 419.1,306.71 419.1,347.35 417.19,349.25 v417.19,354.97 | v414.65,357.5 412.75,359.41 v412.75,374.02
  Bottom 0.254: v417.19,304.8 412.75,300.36 411.48,300.36 411.48,295.91 B08.S2 | v414.65,357.5 v417.19,354.97 | v412.75,374.02 410.85,375.92 403.86,375.92 397.51,382.27 389.89,382.27 388.62,383.54 386.08,383.54 A10.K2
N$167  (via drill 0.61)
  Top 0.254: v302.26,344.81 302.89,345.44 v302.89,354.97
  Route2 0.254: v153.67,338.46 156.21,341 162.56,341 164.47,342.9 218.44,342.9 220.98,345.44 254,345.44 254.63,344.81 296.55,344.81 297.81,346.08 300.99,346.08 v302.26,344.81
  Route3 0.254: v153.67,338.46 152.4,337.19 152.4,314.96 156.84,314.96 B28.K2
  Bottom 0.254: v302.89,354.97 306.07,358.14 309.25,358.14 A16.U2
N$168  (via drill 0.61)
  Top 0.254: v358.77,257.81 358.77,227.33 357.5,226.06 C12.T2
  Bottom 0.254: v358.77,257.81 359.41,258.44 362.58,258.44 363.22,259.08 365.76,259.08 366.39,258.44 371.48,258.44 372.75,259.72 C11.E2
N$169  (via drill 0.61)
  Top 0.254: v184.15,327.66 184.15,346.08 187.32,349.25 v187.32,354.97 | v191.77,359.41 191.77,361.31 A25.T2 | v231.78,356.24 231.78,363.22 233.04,364.49 A22.S2
  Bottom 0.254: v184.15,327.66 183.51,328.3 177.8,328.3 177.8,325.75 179.07,324.49 B26.F2 | v187.32,354.97 v191.77,359.41 197.49,353.7 211.46,353.7 212.72,352.43 231.78,352.43 v231.78,356.24
N$170
  Top 0.254: A23.F2 217.17,394.34 215.9,395.61 215.9,400.69 226.69,411.48 231.78,411.48 231.78,398.78 233.04,397.51 A22.E2
N$171
  Top 0.254: B26.S2 182.25,295.91 180.97,297.18 180.97,299.72 179.71,300.99 179.71,304.17 B26.N2
  Route3 0.254: A25.M2 194.94,377.19 193.68,375.92 193.68,365.76 190.5,362.59 190.5,356.87 180.97,347.35 180.97,306.71 179.71,305.44 B26.N2
N$172  (via drill 0.61)
  Top 0.254: v232.41,379.73 234.95,382.27 234.95,386.72 233.68,387.99 233.68,389.89 A22.H2
  Bottom 0.254: v232.41,379.73 226.69,379.73 226.06,379.1 221.62,379.1 220.98,378.46 A23.M2
N$174  (via drill 0.61)
  Top 0.254: v226.69,363.22 228.6,363.22 228.6,377.19 233.04,381.64 233.04,383.54 A22.K2
  Bottom 0.254: v226.69,363.22 226.06,363.86 219.07,363.86 217.81,362.59 A23.T2
N$175
  Top 0.254: A22.M2 233.68,378.46 238.12,378.46 238.12,386.72 242.57,391.16 242.57,393.06 A21.F2
N$177
  Route3 0.254: A35.H2 68.58,389.89 73.03,389.89 73.03,387.99 80.64,380.37 80.64,378.46 A34.M2
N$178  (via drill 0.61)
  Top 0.254: v97.79,358.78 111.12,345.44 111.12,319.41 114.3,316.23 114.3,313.06 115.57,311.79 B31.L2 | v84.45,365.12 81.28,368.3 81.28,370.84 A34.P2
  Bottom 0.254: v97.79,358.78 93.34,363.22 86.36,363.22 v84.45,365.12 | A34.N2 78.11,374.02 80.01,372.11 80.64,372.11 A34.P2
N$179
  Bottom 0.254: B31.M2 119.38,308.61 123.83,308.61 125.09,309.88 133.99,309.88 134.62,309.25 137.16,309.25 137.79,309.88 146.69,309.88 147.32,309.25 149.86,309.25 150.5,309.88 159.38,309.88 160.02,309.25 162.56,309.25 163.19,309.88 172.09,309.88 172.72,309.25 175.26,309.25 175.9,309.88 184.78,309.88 185.42,309.25 187.96,309.25 188.59,309.88 197.49,309.88 198.12,309.25 200.66,309.25 201.29,309.88 210.19,309.88 210.82,309.25 213.36,309.25 214,309.88 222.88,309.88 223.52,309.25 226.06,309.25 226.69,309.88 235.59,309.88 236.22,309.25 238.76,309.25 239.4,309.88 245.11,309.88 245.75,309.25 251.46,309.25 252.09,309.88 259.71,309.88 260.35,309.25 264.16,309.25 264.8,309.88 269.24,309.88 269.88,309.25 276.86,309.25 277.5,309.88 286.38,309.88 287.02,309.25 288.29,309.25 288.93,309.88 299.08,309.88 299.72,309.25 302.26,309.25 302.89,309.88 311.79,309.88 312.42,309.25 314.96,309.25 315.6,309.88 324.49,309.88 325.12,309.25 327.66,309.25 328.3,309.88 330.2,309.88 332.11,307.98 334.64,307.98 B14.M2
N$180  (via drill 0.61)
  Top 0.254: v109.22,294 111.12,294 v111.12,276.23
  Route2 0.254: v139.7,273.69 141.6,275.59 164.47,275.59 v166.37,273.69
  Route3 0.254: v166.37,273.69 168.91,276.23 180.34,276.23 v180.34,274.32 | v200.03,276.86 204.47,281.31 204.47,285.12 B24.V2
  Bottom 0.254: v109.22,294 108.58,293.37 99.69,293.37 99.06,294 94.61,294 93.98,294.64 B33.S2 | v111.12,276.23 111.76,276.86 136.53,276.86 v139.7,273.69 | v180.34,274.32 180.97,274.96 198.12,274.96 v200.03,276.86
N$181  (via drill 0.61)
  Route2 0.254: v87.63,108.58 120.02,76.2 123.83,76.2 126.36,73.66 187.32,73.66 190.5,70.48 213.36,70.48 214.63,69.22 234.95,69.22 255.27,48.9 264.16,48.9 264.8,49.53 271.78,49.53 278.76,42.55 289.56,42.55 293.37,46.36 300.99,46.36 v302.89,44.45 | v336.55,43.82 337.82,42.55 340.36,42.55 341,43.18 349.88,43.18 350.52,42.55 353.06,42.55 353.69,43.18 362.58,43.18 363.22,42.55 365.76,42.55 369.57,46.36 374.65,46.36 v375.92,47.62
  Route3 0.254: v87.63,108.58 85.72,110.49 85.72,137.16 87,138.43 87,144.78 85.72,146.05 85.72,209.55 79.38,215.9 79.38,273.69 81.92,276.23 81.92,287.66 81.28,288.29 B34.U2 | v375.92,47.62 377.82,49.53 377.82,60.96 380.37,63.5 380.37,65.41 381,66.04 381,89.53 v382.27,90.8
  Bottom 0.254: v302.89,44.45 303.53,43.82 304.8,43.82 305.44,43.18 309.25,43.18 312.42,46.36 314.96,46.36 315.6,45.72 324.49,45.72 325.12,46.36 327.66,46.36 328.3,45.72 333.38,45.72 335.28,43.82 v336.55,43.82 | v382.27,90.8 381.63,90.17 378.46,90.17 376.56,92.07 373.38,92.07 E11.S2
N$182  (via drill 0.61)
  Route2 0.254: v283.85,278.13 282.57,276.86 275.59,276.86 273.69,278.77 226.69,278.77 224.79,276.86 210.82,276.86 207.01,280.67 200.03,280.67 198.75,281.94 117.47,281.94 v113.67,285.75
  Route3 0.254: v283.85,278.13 285.75,280.04 285.75,293.37 284.48,294.64 B18.S2 | v113.67,285.75 104.78,294.64 v104.78,297.81
  Bottom 0.254: v104.78,297.81 104.78,299.72 97.79,299.72 97.16,300.36 92.08,300.36 90.81,299.09 B33.R2
N$183
  Route2 0.254: A36.T2 52.7,362.59 54.61,364.49 55.24,364.49 A36.S2
N$184
  Bottom 0.254: A36.K2 55.24,384.81 53.34,386.72 52.7,386.72 A36.J2
N$185
  Route2 0.254: E05.N2 446.4,102.23 448.31,104.14 448.94,104.14 E05.M2
N$186
  Bottom 0.254: E05.L2 446.4,108.58 448.31,110.49 448.94,110.49 E05.K2
N$187  (via drill 0.61)
  Top 0.254: v271.78,317.5 271.78,314.96 B19.K2 | v393.7,323.85 393.7,323.22 394.97,321.95 394.97,318.14 B09.J2
  Route2 0.254: v271.78,317.5 276.86,322.58 278.76,322.58 279.4,321.95 289.56,321.95 290.19,322.58 291.46,322.58 292.1,321.95 302.26,321.95 302.89,322.58 311.79,322.58 312.42,321.95 313.69,321.95 v315.6,323.85
  Bottom 0.254: v315.6,323.85 316.23,323.22 317.5,323.22 318.13,322.58 321.94,322.58 325.12,325.75 327.66,325.75 328.3,325.12 335.92,325.12 337.19,326.39 339.73,326.39 341,325.12 349.88,325.12 350.52,325.75 353.06,325.75 353.69,325.12 362.58,325.12 363.22,325.75 365.76,325.75 366.39,325.12 375.29,325.12 375.92,325.75 378.46,325.75 379.1,325.12 385.44,325.12 388.62,321.95 391.16,321.95 393.06,323.85 v393.7,323.85
N$188  (via drill 0.61)
  Top 0.254: v441.32,137.16 441.32,128.27 v442.6,127
  Route2 0.254: v390.52,138.43 387.35,138.43 387.35,159.38 386.71,160.02 384.18,160.02 382.9,161.29 D10.R2
  Bottom 0.254: v390.52,138.43 393.7,138.43 394.33,137.79 403.86,137.79 404.5,138.43 406.4,138.43 407.04,137.79 416.56,137.79 417.19,138.43 427.99,138.43 428.62,137.79 429.26,137.79 429.89,138.43 437.51,138.43 438.79,137.16 v441.32,137.16 | v442.6,127 445.13,124.46 445.77,124.46 | 445.77,124.46 448.94,124.46 E05.E2 | 445.77,124.46 445.77,121.28 E05.F2
N$189  (via drill 0.61)
  Top 0.254: v52.07,359.41 53.98,361.31 53.98,375.92 55.24,377.19 A36.M2
  Route2 0.254: v52.07,359.41 27.94,335.28 27.3,335.28 27.3,330.84 B38.D2
N$190
  Top 0.254: B38.R2 27.3,299.09 28.57,300.36 28.57,312.42 29.84,313.69 B38.K2
  Route2 0.254: A36.V2 52.07,354.97 38.1,341 38.1,316.23 34.29,316.23 33.02,314.96 30.48,314.96 B38.K2
N$191  (via drill 0.61)
  Route2 0.254: v278.13,353.7 279.4,352.43 295.27,352.43 296.55,351.16 v306.07,351.16
  Route3 0.254: v244.47,327.66 244.47,344.81 v252.73,353.06
  Bottom 0.254: v244.47,327.66 245.11,328.3 247.01,328.3 250.19,325.12 254.63,325.12 255.27,324.49 B20.F2 | v252.73,353.06 272.42,353.06 273.05,353.7 v278.13,353.7 | v306.07,351.16 306.7,351.79 315.6,351.79 316.87,350.52 322.58,350.52 323.85,351.79 327.66,351.79 328.93,353.06 337.19,353.06 337.82,352.43 342.9,352.43 343.54,353.06 354.96,353.06 356.87,354.97 A12.V2
N$192
  Bottom 0.254: C39.N2 14.61,238.76 16.51,240.66 17.14,240.66 C39.M2
N$193
  Top 0.254: C39.L2 14.61,243.84 15.88,242.57 17.14,242.57 17.14,247.01 C39.K2
N$194
  Top 0.254: C39.T2 14.61,226.06 15.88,227.33 15.88,233.04 17.14,234.31 C39.P2
N$195  (via drill 0.61)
